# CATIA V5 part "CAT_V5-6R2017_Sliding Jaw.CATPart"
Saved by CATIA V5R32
Part number: Sliding Jaw
Bounding box of the stored display mesh (mm): x -32 to 32, y -16 to 16, z -9 to 36
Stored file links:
  D:\PROJECTS\Project 2022\CATIA V5 6R 2022\Resources\Tutorial Files\c16_catia_v5_6r2022_tut\Bench vice\CAT_V5-6R2017_Sliding Jaw.CATPart
  C:\Program Files\Dassault Systemes\B09\intel_a\reffiles\standard\MetricThickPitch.txt
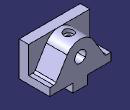
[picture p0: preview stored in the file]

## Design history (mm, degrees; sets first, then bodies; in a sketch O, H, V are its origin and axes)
Body1 (main body)
  Sketch1 on xy-plane, origin (0, 0, 0), H (1, 0, 0), V (0, 1, 0)
    line L1 (-32, -16) -> (32, -16)
    line L2 (32, -16) -> (32, 16)
    line L3 (32, 16) -> (-32, 16)
    line L4 (-32, 16) -> (-32, -16)
    distance H L1 = 16
    distance V L4 = 32
    length L4 = 32
    length L1 = 64
    horizontal: L1 H, L3 H
    vertical: L2 V, L4 V
  Pad1: profile Sketch1, direction (0, 0, 1), length 8
  Sketch2 on face of Pad1, origin (0, -16, 0), H (1, 0, 0), V (0, 0, 1)
    point P1 (-32, 0)
    line L1 (-32, 0) -> (32, 0)
    line L2 (32, 0) -> (32, 36)
    line L3 (32, 36) -> (-32, 36)
    line L4 (-32, 36) -> (-32, 0)
    reference projected line E1 (32, 0) -> (32, 8) from edge of Pad1
    reference projected line E2 (-32, 8) -> (-32, 0) from edge of Pad1
    length L2 = 36
    coincidence: P1 H, L2 E1, L4 E2
    horizontal: L1 H, L3 H
    vertical: L2 V, L4 V
  Pad2: profile Sketch2, direction (0, 1, 0), length 10
  Sketch3 on face of Pad1, origin (0, 16, 0), H (-1, 0, 0), V (0, 0, 1)
    arc A1 centre (0, 20) radius 16 from (13.6777, 28.3018) to (-13.6777, 28.3018) ccw
    point P1 (0, 20)
    reference projected line E1 (-32, 36) -> (32, 36) from edge of Pad2
    line L1 (-26, 8) -> (-13.6777, 28.3018)
    point P2 (-26, 8)
    line L2 (13.6777, 28.3018) -> (26, 8)
    point P3 (26, 8)
    reference projected line E2 (32, 8) -> (-32, 8) from edge of Pad1
    reference projected line E3 (32, 8) -> (-32, 8) from edge of Pad1
    line L3 (-26, 8) -> (26, 8)
    radius A1 = 16
    length L3 = 52
    distance V P3 = 26
    coincidence: P1 V, E2 P2, E3 P3
    tangency: A1 E1, L2 A1, L1 A1
    horizontal: L3 H
  Pad3: profile Sketch3, direction (0, -1, 0), up to the existing solid (limit type 2)
  Fillet1: radius 3, on 2 edges
  Sketch4 on face of Pad1, origin (-2.6964, 16, 22.8197), H (1, 0, 0), V (0, 0, -1)
    point P1 (2.6964, 2.8197)
    reference projected arc E1 centre (2.6964, 2.8197) radius 16 from (-10.9814, -5.4821) to (16.3741, -5.4821) ccw from edge of Pad3
    concentricity: P1 E1
  Hole1: placed by Sketch4, at (0, 16, 20) direction (0, -1, 0), diameter 12, depth 22, V-bottom angle 120
  Sketch5 on face of Pad1, origin (0, 16, 0), H (-1, 0, 0), V (0, 0, 1)
    point P1 (-7.75, 0)
    line L1 (-7.75, 0) -> (7.75, 0)
    line L2 (7.75, 0) -> (7.75, -9)
    line L3 (7.75, -9) -> (-7.75, -9)
    line L4 (-7.75, -9) -> (-7.75, 0)
    distance V L2 = 7.75
    length L3 = 15.5
    length L4 = 9
    coincidence: P1 H
    horizontal: L1 H, L3 H
    vertical: L2 V, L4 V
  Pad4: profile Sketch5, direction (0, -1, 0), length 32
  Sketch6 on face of Pad4, origin (-0.598, -1.2346, -9), H (1, 0, 0), V (0, -1, 0)
    point P1 (0.598, -9.2346)
    reference projected line E1 (8.348, -17.2346) -> (-7.152, -17.2346) from edge of Pad4
    reference projected line E2 (8.348, 14.7654) -> (8.348, -17.2346) from edge of Pad4
    distance P1 E1 = 8
    distance P1 E2 = 7.75
  Hole2: placed by Sketch6, at (0, 8, -9) direction (0, 0, 1), diameter 5, depth 16, V-bottom angle 120, threaded, thread diameter 6, thread depth 16, pitch 1
  RectPattern1: of Hole2, direction 1 instances 2, spacing 16, along edge of Pad4 reversed
  Sketch7 on face of Pad2, origin (-19.6018, -13.7351, 36), H (1, 0, 0), V (0, 1, 0)
    point P1 (19.6018, 17.7351)
    reference intersected line E1 through (19.6018, 0) direction (0, 1) from yz-plane
    reference projected line E2 (51.6018, -2.2649) -> (-12.3982, -2.2649) from edge of Pad2
    distance P1 E2 = 20
    coincidence: E1 P1
  Hole3: placed by Sketch7, at (0, 4, 36) direction (0, 0, -1), diameter 5, depth 16, V-bottom angle 120, counterbore diameter 10, counterbore depth 4, threaded, thread diameter 6, thread depth 11, pitch 1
